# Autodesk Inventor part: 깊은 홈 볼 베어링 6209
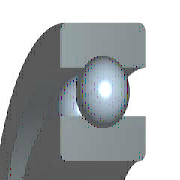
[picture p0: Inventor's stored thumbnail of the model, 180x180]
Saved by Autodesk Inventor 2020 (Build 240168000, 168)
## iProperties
IsCustomPart: 1
Created: 2012-02
Part Number: 깊은 홈 볼 베어링 6209
Material: 강철, 연강
Description: 깊은 그루부 볼 베어링
Document SubType Name: Modeling
Standard: JIS B 1521
Designer: mdu-01
Standards Organization: JIS
Language: ko-KR
Size Designation: 6209 45x85x19
Categories: <MemberInstance><Categories><Category DisplayName="샤프트 부품" InternalName="7f7aeb1f-a693-4053-b835-cee3144e0d98" Mnemonic="SHFT"><Category DisplayName="베어링" Inter
Density: 1 g/cm^3
Appearance: 강철(1)
Author: mdu-01
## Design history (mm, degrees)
sketch "스케치" dims "d0" = 10.4 (= -0.26 x WD + 0.26 x BD)
  geometry: L1 (4.3, 32.5)-(14.7, 32.5); L2 (9.5, 32.5)-(9.5, 27.3); L3 (9.5, 32.5)-(9.5, 37.7); L4 (5.636, 29.02)-(0, 29.02); L5 (0, 22.5)-(19, 22.5); L6 (5.636, 35.98)-(0, 35.98); L7 (0, 42.5)-(19, 42.5); L8 (19, 22.5)-(19, 29.02); L9 (13.364, 29.02)-(19, 29.02); L10 (13.364, 35.98)-(19, 35.98); L11 (19, 42.5)-(19, 35.98); L12 (-1.4, 0)-(8.4, 0) reference; L13 (0, -0.3)-(0, 5.3) reference
  constraints: 22 end point, 4 point on line, 2 collinear, 2 perpendicular, 2 symmetric about line, 1 midpoint, 1 parallel, 14 other
  dimensions: "d9" = 45 diameter of L5 L12 (= WD); "d11" = 85 diameter of L7 L12 (= BD); "d12" = 19 distance between parallel lines of L8 L13 (= KB); "d13" = 58.04 diameter of L9 L12 (= 0.326 x BD + 0.674 x WD)
revolve "본체" stored, may be unused: angle "d6" = 90 deg
revolve "볼" stored, may be unused: angle "d7" = 90 deg
pattern_circular "IDS_ARRAYBALL[SIMPL:T]" dims angle "d3" = 360 deg
body "Solid1"
fillet "모깎기1" dims "d1" = 1.1 (= KRS)
other parameters: "WD" = 45 [user parameter; used in 5 equation terms], "BD" = 85 [user parameter; used in 5 equation terms], "KB" = 19 [user parameter; used in 1 equation term], "KRS" = 1.1 [user parameter; used in 1 equation term], "d4" = 0, "d5" = 0, "d8" = 0, "d14" = 0, "d15" = 0, "BBA" = 0 [user parameter], "BC0" = 2.16e+07 [user parameter], "BC" = 3.32e+07 [user parameter], "BR" = 42.5 (= 0.5 x BD) [user parameter], "WR" = 22.5 (= 0.5 x WD) [user parameter]
